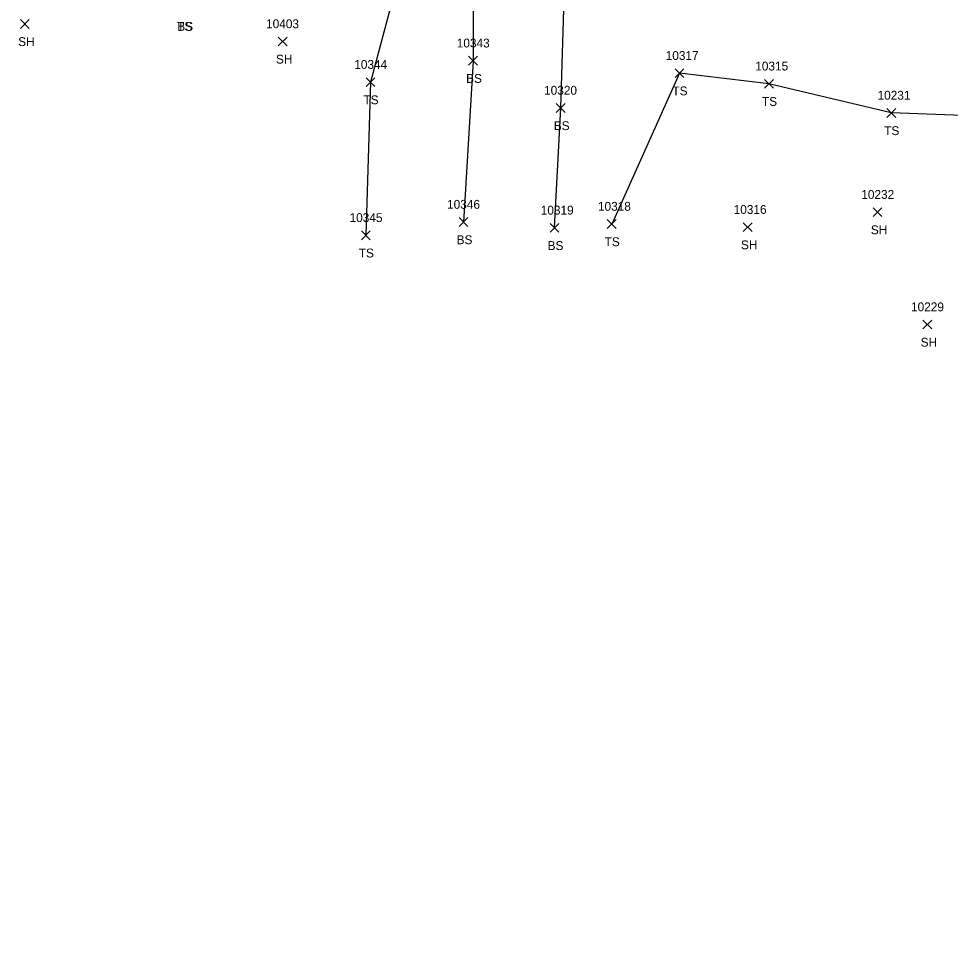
# Model space of a CAD drawing. Extents: x 1475671 to 1477951, y 592661 to 593821.
# Drawn here: x 1476510 to 1476720.5, y 592745.3 to 592957 of the extents above; entities that cross this region are included whole.
import ezdxf

# ---------------------------------------------------------------- set-up
doc = ezdxf.new("R2010")
doc.units = 0
for name, color, linetype in [('L_A', 7, 'Continuous'), ('L_I', 7, 'Continuous'), ('L_TIC', 7, 'Continuous'), ('LELB', 7, 'Continuous')]:
    doc.layers.add(name, color=color, linetype=linetype)

msp = doc.modelspace()

# ---------------------------------------------------------------- linework, layer by layer
at = {"layer": 'L_TIC'}
for points in [[(1476510.37, 592954.78), (1476512.37, 592956.78)], [(1476512.37, 592954.78), (1476510.37, 592956.78)], [(1476568.62, 592950.82), (1476570.62, 592952.82)], [(1476570.62, 592950.82), (1476568.62, 592952.82)], [(1476611.63, 592946.46), (1476613.63, 592948.46)], [(1476613.63, 592946.46), (1476611.63, 592948.46)], [(1476658.28, 592943.64), (1476660.28, 592945.64)], [(1476660.28, 592943.64), (1476658.28, 592945.64)], [(1476588.47, 592941.63), (1476590.47, 592943.63)], [(1476590.47, 592941.63), (1476588.47, 592943.63)], [(1476678.51, 592941.26), (1476680.51, 592943.26)], [(1476680.51, 592941.26), (1476678.51, 592943.26)], [(1476631.45, 592935.79), (1476633.45, 592937.79)], [(1476633.45, 592935.79), (1476631.45, 592937.79)], [(1476706.14, 592934.66), (1476708.14, 592936.66)], [(1476708.14, 592934.66), (1476706.14, 592936.66)], [(1476703.04, 592912.25), (1476705.04, 592914.25)], [(1476705.04, 592912.25), (1476703.04, 592914.25)], [(1476609.49, 592910.01), (1476611.49, 592912.01)], [(1476611.49, 592910.01), (1476609.49, 592912.01)], [(1476630.05, 592908.69), (1476632.05, 592910.69)], [(1476632.05, 592908.69), (1476630.05, 592910.69)], [(1476642.97, 592909.56), (1476644.97, 592911.56)], [(1476644.97, 592909.56), (1476642.97, 592911.56)], [(1476673.69, 592908.86), (1476675.69, 592910.86)], [(1476675.69, 592908.86), (1476673.69, 592910.86)], [(1476587.41, 592907.01), (1476589.41, 592909.01)], [(1476589.41, 592907.01), (1476587.41, 592909.01)], [(1476714.29, 592886.85), (1476716.29, 592888.85)], [(1476716.29, 592886.85), (1476714.29, 592888.85)]]:
    msp.add_lwpolyline(points, dxfattribs=at)
at = {"layer": 'LELB'}
for points in [[(1476807.42, 593044.4), (1476778.65, 593056.41), (1476752.9, 593056.84), (1476722.03, 593058.18), (1476696.31, 593050.53), (1476668.87, 593043.24), (1476656.59, 593046.41), (1476650.8, 593042.11), (1476638.89, 593026.04), (1476625.94, 593005.7), (1476601.98, 592989.57), (1476589.47, 592942.63), (1476588.41, 592908.01)], [(1476656.59, 593046.41), (1476652.52, 593040.43), (1476643.39, 593025.62), (1476634.29, 593003.21), (1476612.62, 592981.81), (1476612.63, 592947.46), (1476610.49, 592911.01)], [(1476631.05, 592909.69), (1476632.45, 592936.79), (1476633.31, 592964.03), (1476656.64, 592987.69)], [(1476851.45, 592745.32), (1476830.58, 592752.29), (1476813.49, 592763.05), (1476796.94, 592780.91), (1476785.16, 592809.74), (1476798.53, 592826.91), (1476776.62, 592865.94), (1476769.27, 592900.93), (1476739.44, 592934.48), (1476707.14, 592935.66), (1476679.51, 592942.26), (1476659.28, 592944.64), (1476643.97, 592910.56)]]:
    msp.add_lwpolyline(points, dxfattribs=at)

# ---------------------------------------------------------------- texts
at = {"layer": 'L_A'}
for s, p in [('TS', (1476545.78, 592954.22)), ('BS', (1476545.81, 592954.22)), ('SH', (1476509.85, 592950.78)), ('SH', (1476568.11, 592946.82)), ('BS', (1476611.07, 592942.46)), ('TS', (1476657.69, 592939.64)), ('TS', (1476587.88, 592937.63)), ('TS', (1476677.92, 592937.26)), ('BS', (1476630.89, 592931.79)), ('TS', (1476705.55, 592930.66)), ('SH', (1476702.53, 592908.25)), ('BS', (1476608.93, 592906.01)), ('BS', (1476629.49, 592904.69)), ('TS', (1476642.38, 592905.56)), ('SH', (1476673.18, 592904.86)), ('TS', (1476586.82, 592903.01)), ('SH', (1476713.78, 592882.85))]:
    msp.add_text(s, height=2, dxfattribs=at).set_placement(p)
at = {"layer": 'L_I'}
for s, p in [('10403', (1476565.87, 592954.82)), ('10343', (1476608.96, 592950.46)), ('10317', (1476656.17, 592947.64)), ('10344', (1476585.8, 592945.63)), ('10315', (1476676.41, 592945.26)), ('10320', (1476628.69, 592939.79)), ('10231', (1476704.04, 592938.66)), ('10232', (1476700.37, 592916.25)), ('10346', (1476606.77, 592914.01)), ('10319', (1476627.94, 592912.69)), ('10318', (1476640.86, 592913.56)), ('10316', (1476671.53, 592912.86)), ('10345', (1476584.74, 592911.01)), ('10229', (1476711.61, 592890.85))]:
    msp.add_text(s, height=2, dxfattribs=at).set_placement(p)

doc.saveas('drawing.dxf')
